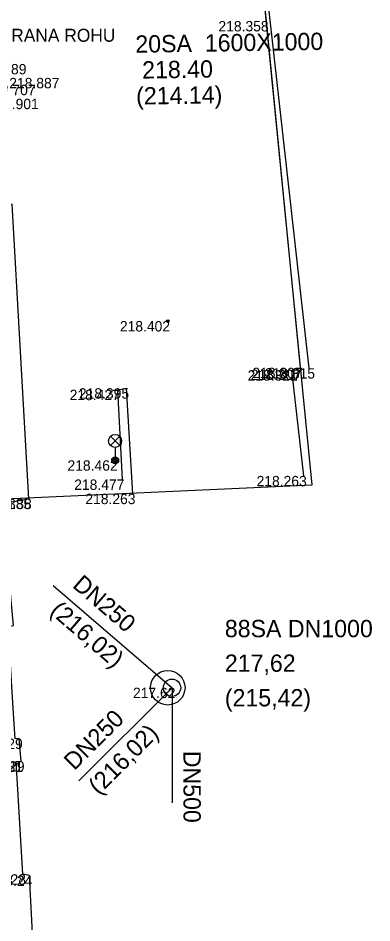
# Model space of a CAD drawing. Extents: x -599516 to -599132, y -1163668 to -1163119.
# Drawn here: x -599229.61 to -599219.39, y -1163388.99 to -1163362.83 of the extents above; entities that cross this region are included whole.
import ezdxf

# ---------------------------------------------------------------- set-up
doc = ezdxf.new("R2010")
doc.units = 0
for name, color, linetype in [('_ZEMERENI OBLAST', 7, 'Continuous'), ('Bod-oznac1', 7, 'Continuous'), ('Bod-vyska1', 7, 'Continuous'), ('Bod-vyska2', 7, 'Continuous'), ('Bod-vyska3', 7, 'Continuous'), ('Z_budovy-obvod', 7, 'Continuous'), ('Z_dopravni-zarizeni-linie-zabradli', 7, 'Continuous'), ('Z_elektro-silno-znacky-lampa', 7, 'Continuous'), ('Z_kanalizace-destova', 7, 'Continuous'), ('Z_kanalizace-znacky-sachta', 7, 'Continuous'), ('Z_podzemni-obrys-sachty', 7, 'Continuous'), ('Z_vol-txt-popis-objektu', 7, 'Continuous'), ('Z_vol-zn-podrobny-vyskovy-bod-geo', 7, 'Continuous'), ('Z_zdi-operna-zarubni', 7, 'Continuous'), ('Z_zpevnene-plochy', 7, 'Continuous')]:
    doc.layers.add(name, color=color, linetype=linetype)

msp = doc.modelspace()

# ---------------------------------------------------------------- linework, layer by layer
at = {"layer": '_ZEMERENI OBLAST'}
msp.add_lwpolyline([(-599224.438, -1163495.846), (-599230.06, -1163390.87), (-599230.844, -1163376.763), (-599221.12, -1163376.319), (-599223.618, -1163350.986), (-599233.018, -1163351.47), (-599238.649, -1163235.236), (-599241.76, -1163178.74), (-599235.422, -1163177.496), (-599237.24, -1163165.98), (-599246.5, -1163164.914), (-599246.21, -1163173.61), (-599310.76, -1163161.2)], dxfattribs=at)
at = {"layer": 'Bod-oznac1'}
for p, q in [((-599222.447, -1163362.914), (-599222.447, -1163362.914)), ((-599225.286, -1163371.588), (-599225.286, -1163371.588)), ((-599221.512, -1163372.992), (-599221.512, -1163372.992)), ((-599221.467, -1163372.938), (-599221.467, -1163372.938)), ((-599221.211, -1163372.95), (-599221.211, -1163372.95)), ((-599221.709, -1163373.008), (-599221.709, -1163373.008)), ((-599226.731, -1163373.574), (-599226.731, -1163373.574)), ((-599226.49, -1163373.53), (-599226.49, -1163373.53)), ((-599226.809, -1163375.613), (-599226.809, -1163375.613)), ((-599221.357, -1163376.064), (-599221.357, -1163376.064)), ((-599226.599, -1163376.167), (-599226.599, -1163376.167)), ((-599226.305, -1163376.58), (-599226.305, -1163376.58)), ((-599229.307, -1163376.723), (-599229.307, -1163376.723)), ((-599229.307, -1163376.723), (-599229.307, -1163376.723)), ((-599225.166, -1163382.187), (-599225.166, -1163382.187)), ((-599229.58, -1163383.659), (-599229.58, -1163383.659)), ((-599229.528, -1163384.313), (-599229.528, -1163384.313)), ((-599229.474, -1163387.58), (-599229.474, -1163387.58)), ((-599229.281, -1163387.617), (-599229.281, -1163387.617))]:
    msp.add_line(p, q, dxfattribs=at)
at = {"layer": 'Z_budovy-obvod'}
for points in [[(-599229.307, -1163376.723), (-599229.782, -1163368.205), (-599230.326, -1163368.249), (-599231.22, -1163368.346), (-599231.227, -1163368.235), (-599231.285, -1163368.237), (-599231.436, -1163368.241), (-599231.798, -1163368.25)], [(-599229.476, -1163390.973), (-599229.108, -1163390.955), (-599229.281, -1163387.617), (-599229.474, -1163387.58), (-599229.666, -1163384.325), (-599229.528, -1163384.313), (-599229.58, -1163383.659), (-599229.695, -1163383.662), (-599229.752, -1163382.776), (-599229.844, -1163381.357), (-599229.92, -1163380.418), (-599229.741, -1163380.392), (-599230.073, -1163376.865), (-599229.307, -1163376.723)]]:
    msp.add_lwpolyline(points, dxfattribs=at)
at = {"layer": 'Z_dopravni-zarizeni-linie-zabradli'}
msp.add_lwpolyline([(-599223.258, -1163355.452), (-599222.447, -1163362.914), (-599221.467, -1163372.938)], dxfattribs=at)
at = {"layer": 'Z_elektro-silno-znacky-lampa'}
for p, q in [((-599226.941, -1163375.183), (-599226.677, -1163374.918)), ((-599226.941, -1163374.918), (-599226.677, -1163375.183)), ((-599226.809, -1163375.238), (-599226.809, -1163375.513))]:
    msp.add_line(p, q, dxfattribs=at)
for centre, radius in [((-599226.809, -1163375.051), 0.188), ((-599226.809, -1163375.613), 0.1), ((-599226.809, -1163375.613), 0.065), ((-599226.809, -1163375.613), 0.03)]:
    msp.add_circle(centre, radius, dxfattribs=at)
at = {"layer": 'Z_kanalizace-destova'}
for p, q in [((-599228.601, -1163379.231), (-599225.166, -1163382.187)), ((-599225.166, -1163382.187), (-599227.859, -1163384.88)), ((-599225.166, -1163382.187), (-599225.166, -1163385.516))]:
    msp.add_line(p, q, dxfattribs=at)
at = {"layer": 'Z_kanalizace-znacky-sachta'}
msp.add_circle((-599225.166, -1163382.187), 0.25, dxfattribs=at)
at = {"layer": 'Z_podzemni-obrys-sachty'}
msp.add_circle((-599225.291, -1163382.187), 0.5, dxfattribs=at)
at = {"layer": 'Z_vol-zn-podrobny-vyskovy-bod-geo'}
for radius in [0.0375, 0.0125]:
    msp.add_circle((-599225.286, -1163371.588), radius, dxfattribs=at)
at = {"layer": 'Z_zdi-operna-zarubni'}
for points in [[(-599221.357, -1163376.064), (-599221.709, -1163373.008), (-599221.512, -1163372.992)], [(-599226.599, -1163376.167), (-599226.731, -1163373.574), (-599226.49, -1163373.53), (-599226.305, -1163376.58)]]:
    msp.add_lwpolyline(points, dxfattribs=at)
at = {"layer": 'Z_zpevnene-plochy'}
msp.add_lwpolyline([(-599223.092, -1163355.698), (-599222.574, -1163360.732), (-599222.783, -1163360.922), (-599222.823, -1163361.175), (-599222.688, -1163361.392), (-599222.493, -1163361.497), (-599221.211, -1163372.95)], dxfattribs=at)

# ---------------------------------------------------------------- texts
at = {"layer": 'Bod-vyska1'}
for s, p in [('218.358', (-599223.825, -1163363.214)), ('218.402', (-599226.673, -1163371.888)), ('218.307', (-599222.89, -1163373.292)), ('218.307', (-599222.845, -1163373.238)), ('218.315', (-599222.485, -1163373.25)), ('218.321', (-599222.983, -1163373.308)), ('218.427', (-599228.122, -1163373.874)), ('218.395', (-599227.856, -1163373.83)), ('218.462', (-599228.187, -1163375.913)), ('218.263', (-599222.723, -1163376.364)), ('218.477', (-599227.992, -1163376.467)), ('218.263', (-599227.671, -1163376.88)), ('218.385', (-599230.685, -1163377.023)), ('218.38', (-599230.445, -1163377.023)), ('217.62', (-599226.294, -1163382.487)), ('218.29', (-599230.706, -1163383.959)), ('218.31', (-599230.7, -1163384.625)), ('218.29', (-599230.654, -1163384.613)), ('218.28', (-599230.612, -1163387.88)), ('218.24', (-599230.43, -1163387.917))]:
    msp.add_text(s, height=0.3, dxfattribs=at).set_placement(p)
at = {"layer": 'Bod-vyska2'}
for s, p in [('218.689', (-599230.821, -1163364.455)), ('218.707', (-599230.558, -1163365.058)), ('218.901', (-599230.466, -1163365.461))]:
    msp.add_text(s, height=0.3, dxfattribs=at).set_placement(p)
at = {"layer": 'Bod-vyska3'}
msp.add_text('218.887', height=0.3, dxfattribs=at).set_placement((-599229.868, -1163364.858))
at = {"layer": 'Z_kanalizace-destova'}
for s, rotation, p in [('20SA  1600X1000', 0.8872, (-599226.222, -1163363.832)), (' 218.40', 0.8872, (-599226.211, -1163364.581)), ('(214.14)', 0.8872, (-599226.199, -1163365.331)), ('DN250', 319.2833, (-599228.069, -1163379.263)), ('(216,02)', 319.2833, (-599228.721, -1163380.021)), ('DN250', 45, (-599227.987, -1163384.602)), ('(216,02)', 45, (-599227.28, -1163385.309)), ('DN500', 270, (-599224.836, -1163384.011))]:
    msp.add_text(s, height=0.5, rotation=rotation, dxfattribs=at).set_placement(p)
for s, p in [('88SA DN1000', (-599223.64, -1163380.727)), ('217,62', (-599223.64, -1163381.727)), ('(215,42)', (-599223.64, -1163382.727))]:
    msp.add_text(s, height=0.5, dxfattribs=at).set_placement(p)
at = {"layer": 'Z_vol-txt-popis-objektu'}
msp.add_text('OCHRANA ROHU', height=0.375, dxfattribs=at).set_placement((-599230.925, -1163363.513))

doc.saveas('drawing.dxf')
